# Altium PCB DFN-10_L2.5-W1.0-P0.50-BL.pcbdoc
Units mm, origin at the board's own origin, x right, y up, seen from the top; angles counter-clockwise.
Board outline 15.67 x 14.99 mm, 2 copper layers (Top Layer, Bottom Layer), stack 0 mm thick; 1 components, 0 nets, 10 pads, 0 vias.
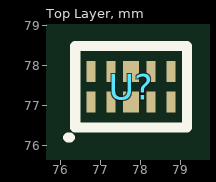
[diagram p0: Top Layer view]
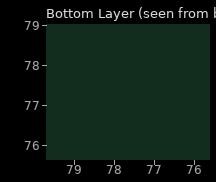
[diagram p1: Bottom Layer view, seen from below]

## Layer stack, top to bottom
Top Layer: signal copper (thickness not stored)
Bottom Layer: signal copper (thickness not stored)

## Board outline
85.521,69.85 69.85,69.85 69.85,84.836 85.521,84.836

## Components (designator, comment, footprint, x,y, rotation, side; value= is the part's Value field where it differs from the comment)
U? "" DFN-10_L2.5-W1.0-P0.50-BL 77.774,77.47 r0 top

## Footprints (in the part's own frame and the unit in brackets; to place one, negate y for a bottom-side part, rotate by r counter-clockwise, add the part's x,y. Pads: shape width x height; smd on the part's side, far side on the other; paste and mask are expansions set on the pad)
DFN-10_L2.5-W1.0-P0.50-BL [mm]
  rect 0.22x0.521 smd: 1(-1,-0.38) 2(-0.5,-0.38) 4(0.5,-0.38) 5(1,-0.38) 6(1,0.38) 7(0.5,0.38) 9(-0.5,0.38) 10(-1,0.38)
  rect 0.4x0.521 smd: 3(0,-0.38) 8(0,0.38)
  silkscreen extent -1.57,-1.27 1.4,1.02

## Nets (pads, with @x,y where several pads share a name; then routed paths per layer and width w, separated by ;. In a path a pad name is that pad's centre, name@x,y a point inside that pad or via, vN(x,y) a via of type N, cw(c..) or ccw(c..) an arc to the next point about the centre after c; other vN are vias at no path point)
pads on no net: U?.1 U?.2 U?.3 U?.4 U?.5 U?.6 U?.7 U?.8 U?.9 U?.10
